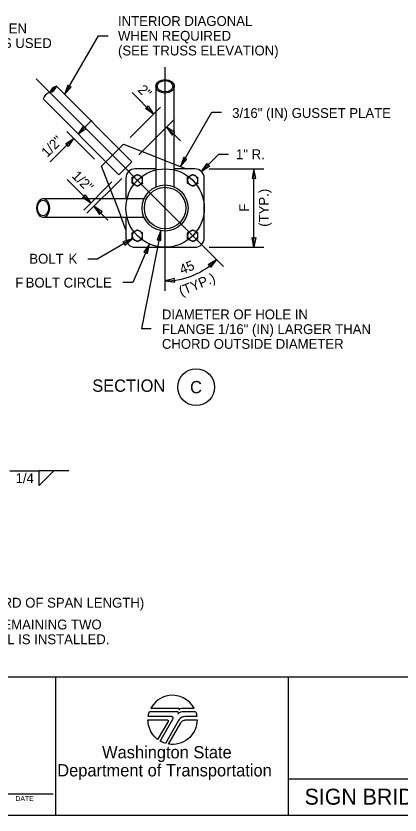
# Model space of a CAD drawing. Extents: x 99862 to 104211, y 98939 to 111076.
# Drawn here: x 101996 to 102621, y 106000 to 107300 of the extents above; entities that cross this region are included whole.
import ezdxf

# ---------------------------------------------------------------- set-up
doc = ezdxf.new("R2010")
doc.units = 0
for name, color, linetype in [('Level 12', 7, 'Continuous'), ('Level 14', 7, 'Continuous'), ('Level 15', 7, 'Continuous'), ('Level 20', 7, 'Continuous'), ('Level 4', 7, 'Continuous'), ('Level 5', 7, 'Continuous'), ('Level 60', 7, 'Continuous'), ('Level 62', 7, 'Continuous'), ('Level 7', 7, 'Continuous'), ('Level 9', 7, 'Continuous')]:
    doc.layers.add(name, color=color, linetype=linetype)

msp = doc.modelspace()

# ---------------------------------------------------------------- linework, layer by layer
at = {"layer": 'Level 12'}
for p, q in [((102163.4, 107084.1), (102170.7, 107091.4)), ((102170.7, 107091.4), (102223.7, 107070.9)), ((102163.4, 107084.2), (102142.2, 107062.9)), ((102135, 107055.7), (102142.3, 107063)), ((102223.7, 107070.9), (102253.7, 107059.2)), ((102155.5, 107002.7), (102135, 107055.7)), ((102253.7, 107059.2), (102273.8, 107051.4)), ((102155.5, 107002.7), (102167.1, 106972.7)), ((102174.9, 106952.5), (102167.1, 106972.7))]:
    msp.add_line(p, q, dxfattribs=at)
at = {"layer": 'Level 14'}
for p, q in [((102223.7, 107051.4), (102189.9, 107051.4)), ((102287.4, 107051.4), (102253.7, 107051.4)), ((102174.9, 107036.4), (102174.9, 107002.7)), ((102302.4, 106938.9), (102302.4, 107036.4)), ((102174.9, 106972.7), (102174.9, 106938.9)), ((102189.9, 106923.9), (102287.4, 106923.9))]:
    msp.add_line(p, q, dxfattribs=at)
for centre, start, end in [((102189.9, 107036.4), 90, 180), ((102287.4, 107036.4), 0, 90), ((102189.9, 106938.9), 180, 270), ((102287.4, 106938.9), 270, 0)]:
    msp.add_arc(centre, 15, start, end, dxfattribs=at)
at = {"layer": 'Level 15'}
for p, q in [((102075, 107172.6), (102130, 107268)), ((102130, 107268), (102146, 107268)), ((102238.7, 106853), (102238.7, 107217.1)), ((102333.9, 106892.5), (102028.6, 107197.8)), ((102184.9, 107175.7), (102219.9, 107140.7)), ((102182, 107102.7), (102231.3, 107152)), ((102263.8, 107055.3), (102314.7, 107143.5)), ((102314.7, 107143.5), (102330.7, 107143.5)), ((102097, 107108.2), (102119.6, 107130.8)), ((102195.9, 107074.2), (102252.5, 107130.8)), ((102123.7, 107067), (102078.4, 107112.3)), ((102241.2, 107119.5), (102263.8, 107096.8)), ((102089.7, 107101), (102051.6, 107062.8)), ((102298, 107047), (102326.2, 107075.2)), ((102326.2, 107075.2), (102342.2, 107075.2)), ((102310.4, 107051.4), (102399.4, 107051.4)), ((102383.4, 106923.9), (102383.4, 107051.4)), ((102079, 107034.3), (102117.5, 106995.8)), ((102168, 107035.7), (102111.5, 106979.2)), ((102152.2, 107030.5), (102106.2, 106984.5)), ((102122.8, 106990.5), (102145.4, 106967.8)), ((102231.5, 106950.9), (102200.2, 106791.8)), ((102185.2, 106937.7), (102128.9, 106905.2)), ((102213.3, 106929.2), (102186, 106866.3)), ((102310.4, 106923.9), (102399.4, 106923.9)), ((102112.9, 106905.2), (102128.9, 106905.2)), ((102186, 106866.3), (102170, 106866.3)), ((102200.2, 106791.8), (102216.2, 106791.8)), ((101985.7, 106560.1), (102033.7, 106560.1)), ((102033.7, 106536.1), (102033.7, 106560.1)), ((102033.7, 106536.1), (102057.7, 106560.1)), ((102081.7, 106560.1), (102033.7, 106560.1))]:
    msp.add_line(p, q, dxfattribs=at)
for points in [[(102075, 107172.6), (102085.5, 107184.7), (102082.5, 107185.6), (102080.2, 107187.8)], [(102219.9, 107140.7), (102206.6, 107149.6), (102209.3, 107151.3), (102211, 107154)], [(102097, 107108.2), (102110.3, 107117.1), (102107.6, 107118.8), (102105.9, 107121.5)], [(102241.2, 107119.5), (102250.1, 107106.2), (102251.8, 107108.9), (102254.5, 107110.5)], [(102089.7, 107101), (102080.8, 107087.7), (102079.1, 107090.4), (102076.4, 107092)], [(102263.8, 107055.3), (102274.3, 107067.4), (102271.3, 107068.3), (102269, 107070.5)], [(102298, 107047), (102307, 107060.3), (102308.7, 107057.6), (102311.3, 107056)], [(102383.4, 107051.4), (102380.4, 107035.7), (102383.4, 107036.4), (102386.5, 107035.7)], [(102117.5, 106995.8), (102104.2, 107004.7), (102106.9, 107006.4), (102108.5, 107009.1)], [(102122.8, 106990.5), (102131.7, 106977.2), (102133.4, 106979.9), (102136.1, 106981.5)], [(102231.5, 106950.9), (102225.6, 106936), (102228.8, 106936.1), (102231.7, 106934.9)], [(102185.2, 106937.7), (102170, 106932.6), (102172.2, 106930.3), (102173.1, 106927.2)], [(102383.4, 106923.9), (102380.4, 106939.7), (102383.4, 106938.9), (102386.5, 106939.7)], [(102213.3, 106929.2), (102204.2, 106916), (102207.3, 106915.5), (102209.9, 106913.6)], [(102322.6, 106903.8), (102312.8, 106891.1), (102311.4, 106893.9), (102308.8, 106895.7)], [(102238.7, 106869), (102254.6, 106866.9), (102253.7, 106870), (102254.2, 106873.1)]]:
    msp.add_lwpolyline(points, close=True, dxfattribs=at)
msp.add_circle((102238.7, 106987.7), 63.8, dxfattribs=at)
msp.add_arc((102238.7, 106987.7), 118.7, 269.9991, 315, dxfattribs=at)
at = {"layer": 'Level 4'}
for p, q in [((102204.3, 107002.7), (102039.9, 107002.7)), ((102039.9, 106972.7), (102204.3, 106972.7))]:
    msp.add_line(p, q, dxfattribs=at)
for radius in [37.5, 33.8]:
    msp.add_circle((102238.7, 106987.7), radius, dxfattribs=at)
for centre, start_param, end_param in [((102039.9, 106987.7), 0, 3.141593), ((102040.1, 106987.7), 3.141593, 6.283185)]:
    msp.add_ellipse(centre, major_axis=(0, 15), ratio=0.707107, start_param=start_param, end_param=end_param, dxfattribs=at)
msp.add_ellipse((102039.9, 106987.7), major_axis=(0, 12.7), ratio=0.707107, dxfattribs=at)
at = {"layer": 'Level 5'}
for p, q in [((102223.7, 107185.8), (102223.7, 107022)), ((102253.7, 107022), (102253.7, 107185.8))]:
    msp.add_line(p, q, dxfattribs=at)
for major_axis in [(15, 0), (12.7, 0)]:
    msp.add_ellipse((102238.7, 107185.8), major_axis=major_axis, ratio=0.729171, dxfattribs=at)
at = {"layer": 'Level 60'}
for p, q in [((100000, 106225), (103150, 106225)), ((102060.1, 106225), (102060.1, 106000)), ((102439.1, 106225), (102439.1, 106000)), ((102439.1, 106059.1), (103039.1, 106059.1)), ((101954.4, 106034.6), (102056.6, 106034.6)), ((100000, 106000), (103150, 106000))]:
    msp.add_line(p, q, dxfattribs=at)
for points in [[(102215.6, 106173.9), (102259.9, 106173.9), (102260.7, 106173.7), (102261.4, 106173.2), (102261.7, 106172.6), (102261.7, 106172), (102261.5, 106171.2), (102262.3, 106172.2), (102263.5, 106173.1), (102265.2, 106173.8), (102266.4, 106173.9), (102285.9, 106173.9), (102283, 106178.5), (102278.9, 106183.3), (102273.7, 106187.6), (102268.3, 106190.8), (102263.3, 106192.8), (102257.6, 106194.2), (102251.6, 106194.8), (102245.1, 106194.4), (102239.7, 106193.3), (102235.1, 106191.6), (102231.1, 106189.6), (102227.3, 106187.2), (102223.7, 106184.3), (102219.8, 106180.1), (102217.5, 106176.9)], [(102215.6, 106173.9), (102259.9, 106173.9), (102260.7, 106173.7), (102261.4, 106173.2), (102261.7, 106172.6), (102261.7, 106172), (102261.5, 106171.2), (102262.3, 106172.2), (102263.5, 106173.1), (102265.2, 106173.8), (102266.4, 106173.9), (102285.9, 106173.9), (102283, 106178.5), (102278.9, 106183.3), (102273.7, 106187.6), (102268.3, 106190.8), (102263.3, 106192.8), (102257.6, 106194.2), (102251.6, 106194.8), (102245.1, 106194.4), (102239.7, 106193.3), (102235.1, 106191.6), (102231.1, 106189.6), (102227.3, 106187.2), (102223.7, 106184.3), (102219.8, 106180.1), (102217.5, 106176.9)], [(102213.3, 106168.7), (102257.2, 106168.7), (102257.9, 106168.6), (102258.5, 106168.4), (102258.9, 106168.2), (102259.2, 106167.9), (102259.7, 106167.3), (102260, 106166.6), (102260.2, 106165.9), (102260.1, 106165.2), (102260, 106164.7), (102259.7, 106164.2), (102260.2, 106164.9), (102261.1, 106165.9), (102262.1, 106166.8), (102263.4, 106167.6), (102264.6, 106168.1), (102266.5, 106168.6), (102269.2, 106168.7), (102288.3, 106168.7), (102289.1, 106166.2), (102289.6, 106164.5), (102290, 106162.7), (102290.3, 106160.9), (102290.4, 106160.1), (102272, 106160.1), (102269.5, 106160), (102267.7, 106159.7), (102265.2, 106158.7), (102263.2, 106157.2), (102261.8, 106155.7), (102260.6, 106153.7), (102239.1, 106116.6), (102236.5, 106117.5), (102234.2, 106118.5), (102232.2, 106119.5), (102230.7, 106120.3), (102251.5, 106156.1), (102251.9, 106157.4), (102251.6, 106158.6), (102250.7, 106159.6), (102249.9, 106160), (102249.3, 106160.1), (102211.2, 106160.1), (102211.6, 106162.6), (102211.8, 106163.9), (102212.2, 106165.3), (102212.7, 106167)], [(102210.8, 106154.8), (102242.3, 106154.8), (102242.7, 106154.8), (102243.2, 106154.6), (102243.5, 106154.4), (102243.7, 106154.1), (102243.9, 106153.7), (102243.9, 106153.3), (102243.9, 106152.9), (102243.7, 106152.4), (102226.6, 106123), (102224.5, 106124.7), (102222.6, 106126.5), (102220.7, 106128.5), (102218.3, 106131.5), (102216.6, 106134.1), (102215, 106137), (102213.6, 106140.2), (102212.6, 106143), (102211.8, 106146), (102211.2, 106149), (102210.9, 106152)], [(102244.2, 106115.4), (102264.2, 106150), (102264.8, 106150.9), (102265.4, 106151.6), (102266.3, 106152.5), (102267.2, 106153.2), (102268.3, 106153.8), (102269.5, 106154.3), (102270.8, 106154.6), (102271.5, 106154.7), (102272.4, 106154.7), (102290.8, 106154.7), (102290.5, 106150.3), (102290, 106146.9), (102288.8, 106142.5), (102287.6, 106139.3), (102286, 106135.9), (102283.5, 106131.9), (102280.8, 106128.4), (102278.9, 106126.4), (102276.1, 106123.9), (102272.7, 106121.4), (102268.7, 106119.1), (102265, 106117.5), (102260.9, 106116.2), (102256.9, 106115.3), (102252.4, 106114.9), (102249.2, 106114.9), (102246.3, 106115.1)]]:
    msp.add_lwpolyline(points, close=True, dxfattribs=at)
at = {"layer": 'Level 7'}
for p, q in [((102184.6, 107062.9), (102061.8, 107185.8)), ((102039.9, 107165.2), (102163.4, 107041.7)), ((102163.5, 107041.8), (102184.6, 107062.9))]:
    msp.add_line(p, q, dxfattribs=at)
for centre, radius, start, end in [((102065.2, 107171.2), 15, 103.1831, 163.1831), ((102047.4, 107190.1), 15, 283.1831, 343.1831), ((102065.2, 107171.2), 12.7, 111.104, 155.2621), ((102054.3, 107160.9), 15, 103.1831, 163.1831)]:
    msp.add_arc(centre, radius, start, end, dxfattribs=at)
at = {"layer": 'Level 9'}
for p, q in [((102189.3, 107040), (102189.5, 107040.1)), ((102279.5, 107040), (102279.7, 107040.1)), ((102185.2, 107032.5), (102185.2, 107033)), ((102189.6, 107025.3), (102189.2, 107025.6)), ((102198, 107025.5), (102197.7, 107025.4)), ((102275.4, 107032.5), (102275.4, 107033)), ((102279.8, 107025.3), (102279.4, 107025.6)), ((102288.2, 107025.5), (102287.9, 107025.4)), ((102189.3, 106949.8), (102189.5, 106950)), ((102279.5, 106949.8), (102279.7, 106950)), ((102185.2, 106942.4), (102185.2, 106942.8)), ((102189.6, 106935.2), (102189.2, 106935.4)), ((102198, 106935.4), (102197.7, 106935.2)), ((102275.4, 106942.4), (102275.4, 106942.8)), ((102279.8, 106935.2), (102279.4, 106935.4)), ((102288.2, 106935.4), (102287.9, 106935.2))]:
    msp.add_line(p, q, dxfattribs=at)
msp.add_circle((102289.3, 106696.3), 30, dxfattribs=at)
for centre, start, end in [((102193.6, 107032.8), 120.758, 178.5832), ((102193.6, 107032.8), 0, 119.2446), ((102283.8, 107032.8), 120.758, 178.5832), ((102283.8, 107032.8), 0, 119.2446), ((102193.6, 107032.8), 181.4168, 238.4392), ((102193.6, 107032.8), 241.5608, 298.8031), ((102193.6, 107032.8), 301.1969, 0), ((102283.8, 107032.8), 181.4168, 238.4392), ((102283.8, 107032.8), 241.5608, 298.8031), ((102283.8, 107032.8), 301.1969, 0), ((102193.6, 106942.6), 120.758, 178.5832), ((102193.6, 106942.6), 0, 119.2446), ((102283.8, 106942.6), 120.758, 178.5832), ((102283.8, 106942.6), 0, 119.2446), ((102193.6, 106942.6), 181.4168, 238.4392), ((102193.6, 106942.6), 241.5608, 298.8031), ((102193.6, 106942.6), 301.1969, 0), ((102283.8, 106942.6), 181.4168, 238.4392), ((102283.8, 106942.6), 241.5608, 298.8031), ((102283.8, 106942.6), 301.1969, 0)]:
    msp.add_arc(centre, 8.44, start, end, dxfattribs=at)
for points, degree in [([(102185.2, 107037.6), (102186.6, 107038.4), (102187.9, 107039.2), (102189.3, 107040)], 2), ([(102185.2, 107033), (102185.2, 107033.7), (102185.2, 107034.5), (102185.2, 107036.1), (102185.2, 107036.9), (102185.2, 107037.6)], 3), ([(102189.5, 107040.1), (102190.9, 107040.9), (102192.3, 107041.7), (102193.6, 107042.5)], 2), ([(102193.6, 107042.5), (102195, 107041.7), (102196.4, 107040.9), (102199.3, 107039.2), (102200.7, 107038.4), (102202.1, 107037.6)], 3), ([(102202.1, 107032.8), (102202.1, 107033.6), (102202.1, 107034.4), (102202.1, 107036), (102202.1, 107036.8), (102202.1, 107037.6)], 3), ([(102275.4, 107037.6), (102276.7, 107038.4), (102278.1, 107039.2), (102279.5, 107040)], 2), ([(102275.4, 107033), (102275.4, 107033.7), (102275.4, 107034.5), (102275.4, 107036.1), (102275.4, 107036.9), (102275.4, 107037.6)], 3), ([(102279.7, 107040.1), (102281.1, 107040.9), (102282.5, 107041.7), (102283.8, 107042.5)], 2), ([(102283.8, 107042.5), (102285.2, 107041.7), (102286.6, 107040.9), (102289.4, 107039.2), (102290.9, 107038.4), (102292.2, 107037.6)], 3), ([(102292.2, 107032.8), (102292.2, 107033.6), (102292.2, 107034.4), (102292.2, 107036), (102292.2, 107036.8), (102292.2, 107037.6)], 3), ([(102185.2, 107027.9), (102185.2, 107029.4), (102185.2, 107031), (102185.2, 107032.5)], 2), ([(102189.2, 107025.6), (102187.9, 107026.4), (102186.5, 107027.1), (102185.2, 107027.9)], 2), ([(102193.6, 107023), (102192.3, 107023.8), (102191, 107024.5), (102189.6, 107025.3)], 2), ([(102197.7, 107025.4), (102196.3, 107024.6), (102195, 107023.8), (102193.6, 107023)], 2), ([(102202.1, 107027.9), (102200.7, 107027.1), (102199.4, 107026.3), (102198, 107025.5)], 2), ([(102202.1, 107027.9), (102202.1, 107029.5), (102202.1, 107031.1), (102202.1, 107032.8)], 2), ([(102275.4, 107027.9), (102275.4, 107029.4), (102275.4, 107031), (102275.4, 107032.5)], 2), ([(102279.4, 107025.6), (102278, 107026.4), (102276.7, 107027.1), (102275.4, 107027.9)], 2), ([(102283.8, 107023), (102282.5, 107023.8), (102281.1, 107024.5), (102279.8, 107025.3)], 2), ([(102287.9, 107025.4), (102286.5, 107024.6), (102285.1, 107023.8), (102283.8, 107023)], 2), ([(102292.2, 107027.9), (102290.9, 107027.1), (102289.6, 107026.3), (102288.2, 107025.5)], 2), ([(102292.2, 107027.9), (102292.2, 107029.5), (102292.2, 107031.1), (102292.2, 107032.8)], 2), ([(102185.2, 106947.5), (102186.6, 106948.2), (102187.9, 106949), (102189.3, 106949.8)], 2), ([(102185.2, 106942.8), (102185.2, 106943.6), (102185.2, 106944.4), (102185.2, 106945.9), (102185.2, 106946.7), (102185.2, 106947.5)], 3), ([(102189.5, 106950), (102190.9, 106950.8), (102192.3, 106951.6), (102193.6, 106952.3)], 2), ([(102193.6, 106952.3), (102195, 106951.5), (102196.4, 106950.7), (102199.3, 106949.1), (102200.7, 106948.3), (102202.1, 106947.5)], 3), ([(102202.1, 106942.6), (102202.1, 106943.4), (102202.1, 106944.3), (102202.1, 106945.9), (102202.1, 106946.7), (102202.1, 106947.5)], 3), ([(102275.4, 106947.5), (102276.7, 106948.2), (102278.1, 106949), (102279.5, 106949.8)], 2), ([(102275.4, 106942.8), (102275.4, 106943.6), (102275.4, 106944.4), (102275.4, 106945.9), (102275.4, 106946.7), (102275.4, 106947.5)], 3), ([(102279.7, 106950), (102281.1, 106950.8), (102282.5, 106951.6), (102283.8, 106952.3)], 2), ([(102283.8, 106952.3), (102285.2, 106951.5), (102286.6, 106950.7), (102289.4, 106949.1), (102290.9, 106948.3), (102292.2, 106947.5)], 3), ([(102292.2, 106942.6), (102292.2, 106943.4), (102292.2, 106944.3), (102292.2, 106945.9), (102292.2, 106946.7), (102292.2, 106947.5)], 3), ([(102185.2, 106937.7), (102185.2, 106939.2), (102185.2, 106940.8), (102185.2, 106942.4)], 2), ([(102189.2, 106935.4), (102187.9, 106936.2), (102186.5, 106937), (102185.2, 106937.7)], 2), ([(102193.6, 106932.9), (102192.3, 106933.6), (102191, 106934.4), (102189.6, 106935.2)], 2), ([(102197.7, 106935.2), (102196.3, 106934.4), (102195, 106933.6), (102193.6, 106932.9)], 2), ([(102202.1, 106937.7), (102200.7, 106937), (102199.4, 106936.2), (102198, 106935.4)], 2), ([(102202.1, 106937.7), (102202.1, 106939.3), (102202.1, 106940.9), (102202.1, 106942.6)], 2), ([(102275.4, 106937.7), (102275.4, 106939.2), (102275.4, 106940.8), (102275.4, 106942.4)], 2), ([(102279.4, 106935.4), (102278, 106936.2), (102276.7, 106937), (102275.4, 106937.7)], 2), ([(102283.8, 106932.9), (102282.5, 106933.6), (102281.1, 106934.4), (102279.8, 106935.2)], 2), ([(102287.9, 106935.2), (102286.5, 106934.4), (102285.1, 106933.6), (102283.8, 106932.9)], 2), ([(102292.2, 106937.7), (102290.9, 106937), (102289.6, 106936.2), (102288.2, 106935.4)], 2), ([(102292.2, 106937.7), (102292.2, 106939.3), (102292.2, 106940.9), (102292.2, 106942.6)], 2)]:
    msp.add_open_spline(points, degree=degree, dxfattribs=at)

# ---------------------------------------------------------------- texts
at = {"layer": 'Level 15'}
for s, p in [('INTERIOR DIAGONAL', (102162, 107284)), ('WHEN REQUIRED', (102162, 107260)), ('(SEE TRUSS ELEVATION) ', (102162, 107236)), ('3/16" (IN) GUSSET PLATE', (102348, 107134.3)), ('DIAMETER OF HOLE IN', (102233.5, 106806.6)), ('FLANGE 1/16" (IN) LARGER THAN', (102233.5, 106782.6)), ('CHORD OUTSIDE DIAMETER', (102233.5, 106758.6))]:
    msp.add_text(s, height=16, dxfattribs=at).set_placement(p)
msp.add_text('1/4', height=16, rotation=360, dxfattribs=at).set_placement((101995.2, 106540.1))
at = {"layer": 'Level 20'}
for s, height, p in [('HORIZONTAL DIAGONAL WHEN', 16, (101688, 107272.1)), ('ALTERNATE JOINT DETAIL IS USED', 16, (101688, 107248.1)), ('1" R.', 16, (102354.2, 107067.2)), ('BOLT    ', 16, (102017.6, 106897.2)), ('K', 16, (102081.4, 106897.2)), ('F', 16, (101994.7, 106858.3)), ('   BOLT CIRCLE', 16, (101993.8, 106858.3)), ('SECTION', 20, (102120.1, 106688.7)), ('C', 20, (102279.4, 106686.3)), ('(NO CHORD FIELD SPLICE PERMITTED IN MIDDLE THIRD OF SPAN LENGTH)', 16, (101417.7, 106337.5)), ('3/16" (IN) SHIMS ARE REQUIRED AT THE REMAINING TWO', 16, (101537, 106302)), ('CHORD JOINTS WHEN INTERIOR DIAGONAL IS INSTALLED.', 16, (101537, 106278))]:
    msp.add_text(s, height=height, dxfattribs=at).set_placement(p)
for s, rotation, p in [('2"', 315, (102193.1, 107178.8)), ('1/2"', 45, (102046.7, 107069.2)), ('1/2"', 315, (102085.7, 107038.8)), ('(TYP.)', 90, (102407.4, 106957.2)), ('F', 90, (102375.4, 106981.6)), ('45', 22.4994, (102266.2, 106879.3)), ('(TYP.)', 22.4994, (102265.1, 106844.2))]:
    msp.add_text(s, height=16, rotation=rotation, dxfattribs=at).set_placement(p)
at = {"layer": 'Level 60'}
for s, height, p in [('Washington State', 19.999, (102136.1, 106092.2)), ('Department of Transportation', 19.999, (102063.1, 106062.8)), ('DATE', 8.03, (101995.1, 106022.8))]:
    msp.add_text(s, height=height, dxfattribs=at).set_placement(p)
at = {"layer": 'Level 62'}
msp.add_text('SIGN BRIDGE (TRUSS-TYPE)', height=26, dxfattribs=at).set_placement((102465.9, 106016.8))

doc.saveas('drawing.dxf')
